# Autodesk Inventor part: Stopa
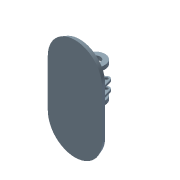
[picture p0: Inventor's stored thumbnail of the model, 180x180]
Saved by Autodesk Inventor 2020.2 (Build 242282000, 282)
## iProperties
Created: 2005-10
Part Number: Stopa
Document SubType Name: Modeling
Designer: F.Stasiak
Density: 1 g/cm^3
Material: Ogólny
Appearance: Niebieski pastelowy
Manager: www.cadconsulting.pl
Company: Fabian Stasiak CAD Consulting
Author: F.Stasiak
Subject: Zbiór ćwiczeń. Autodesk Inventor 2020. Kurs podstawowy
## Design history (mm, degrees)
sketch "Szkic1"
  geometry: L1 (-60, 0)-(-60, -100); L2 (-60, -100)-(60, -100); L3 (60, -100)-(60, 0); C1 r 30 at (0, 0); A1 r 60 centre (0, 0) between (-60, 0) and (60, 0); 1 further point
  constraints: 6 end point, 2 centre point, 2 coincident, 2 point on circle, 2 tangent, 2 vertical, 1 perpendicular
  dimensions: "d0" = 60 diameter of C1; "d1" = 120 diameter of A1; "d2" = 100 distance from line of A1.centre L2
extrude "Wyciągnięcie proste1" new body sketch "Szkic1" distance "d3" = 25; taper "d4" = 0 deg
node "Płaszczyzna konstrukcyjna1"
mirror "Lustro1"
sketch "Szkic5"
  geometry: L1 (120, 25)-(0, 25) reference; L2 (0, 0)-(0, 25) reference; L3 (0, 0)-(120, 0) reference; L4 (120, 0)-(120, 25) reference; L5 (-100, -275)-(-100, 25); L6 (220, 25)-(220, -275); A1 r 160 centre (60, 25) between (220, 25) and (-100, 25); A2 r 160 centre (60, -275) between (-100, -275) and (220, -275); 1 further point
  constraints: 4 end point, 4 point on circle, 4 tangent, 2 centre point, 2 parallel, 1 coincident, 1 midpoint
  dimensions: "d18" = 160 radius of A1; "d19" = 300 distance of L5.start L5.end
extrude "Wyciągnięcie proste5" join sketch "Szkic5" distance "d20" = 30; taper "d21" = 20 deg
sketch "Szkic6"
  geometry: L1 (160, -100)-(-160, -100) reference; L2 (-160, -100)-(-147.895, -54.824); L3 (-109.258, -54.824)-(-97.153, -100); L4 (-160, -100)-(-97.153, -100); L5 (-128.577, -60)-(-128.577, -100); C1 r 10 at (-128.577, -60); A1 r 20 centre (-128.577, -60) between (-109.258, -54.824) and (-147.895, -54.824)
  constraints: 8 end point, 2 centre point, 2 coincident, 2 point on circle, 2 tangent, 1 collinear, 1 midpoint, 1 perpendicular, 1 point on line, 1 other
  dimensions: "d22" = 20 radius of A1; "d23" = 40 distance from line of L1 A1.centre; "d24" = 20 diameter of C1; "d25" = 30 deg angle of L3 L2
extrude "Wyciągnięcie proste6" join sketch "Szkic6" distance "d27" = 15; taper "d28" = 0 deg
node "Płaszczyzna konstrukcyjna2"
mirror "Lustro3"
node "Bryła1"
node "Korpusy bryłowe"
node "Korpusy powierzchniowe"
node "Pętla rzutowana1"
other parameters: "d5" = 85
